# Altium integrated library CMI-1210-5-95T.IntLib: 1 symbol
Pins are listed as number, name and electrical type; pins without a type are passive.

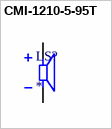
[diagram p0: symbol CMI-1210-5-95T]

## CMI-1210-5-95T
designator LS?
12 mm, 5 Vdc, 98 dB, Through Hole, Magnetic Audio Indicator Buzzer; MF: Same Sky; MP: CMI-1210-5-95T
footprint XDCR_CMI-1210-5-95T
pins: N, P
